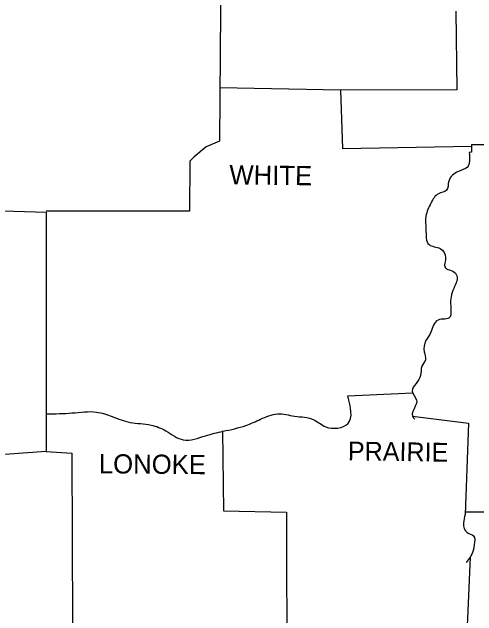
# Model space of a CAD drawing. Extents: x -117616 to 64730, y 54117 to 789866.
# Drawn here: x 64309.8 to 64418.4, y 55726 to 55867.2 of the extents above; entities that cross this region are included whole.
import ezdxf

# ---------------------------------------------------------------- set-up
doc = ezdxf.new("R2010")
doc.units = 0
doc.layers.add('Default', color=7, linetype='Continuous')

msp = doc.modelspace()

# ---------------------------------------------------------------- linework, layer by layer
at = {"layer": 'Default'}
msp.add_line((64417.14, 55836.2), (64429.57, 55836.2), dxfattribs=at)
for points in [[(64310.85, 56002.94), (64311.06, 55978.09), (64309.29, 55977.99), (64309.6, 55951.99), (64302.29, 55950.94), (64302.92, 55943.95), (64305.42, 55940.71), (64305.21, 55932.46), (64291.01, 55931.94), (64290.49, 55919.2), (64277.54, 55918.79), (64276.92, 55903.33), (64277.65, 55902.08), (64277.96, 55877.44), (64300.31, 55875.98), (64299.99, 55820.95), (64317.74, 55820.43), (64317.74, 55764.47), (64303.75, 55763.43), (64302.71, 55751.1), (64279.21, 55751)], [(64300.31, 55875.98), (64353.97, 55875.67), (64358.57, 55877.86), (64358.25, 55837.03), (64355.12, 55835.68), (64352.3, 55833.28), (64351.36, 55832.34), (64351.26, 55820.64), (64317.74, 55820.64)], [(64413.49, 55867.42), (64413.7, 55849.04), (64386.55, 55848.94), (64358.35, 55849.46)], [(64386.55, 55848.94), (64386.97, 55835.26), (64417.14, 55835.8)], [(64417.14, 55836.2), (64417.14, 55834.42), (64416.62, 55834.32)], [(64456.82, 55822.21), (64458.39, 55764.99), (64433.54, 55764.89), (64433.43, 55762.59), (64426.23, 55762.17), (64425.6, 55750.27), (64415.7, 55750.27)], [(64388.22, 55777.42), (64403.46, 55778.15)], [(64403.36, 55772.72), (64416.41, 55771.05), (64415.68, 55749.75)], [(64358.99, 55769.27), (64359.19, 55750.58), (64373.92, 55750.27), (64374.02, 55710.18)], [(64317.74, 55764.47), (64323.8, 55764.05), (64323.9, 55724.17), (64318.47, 55701.51), (64330.06, 55700.99), (64329.96, 55681.03)], [(64416.83, 55739.72), (64415.58, 55711.12), (64407.01, 55710.18), (64407.22, 55701.72), (64410.67, 55701.82), (64410.77, 55698.9), (64415.47, 55698.38), (64415.63, 55693.34)]]:
    msp.add_lwpolyline(points, dxfattribs=at)
for points in [[(64416.62, 55834.32), (64416.1, 55830.87), (64414.12, 55829.93), (64411.82, 55827.64), (64411.3, 55825.55), (64409.42, 55824.71), (64407.64, 55822.52), (64406.49, 55819.49), (64406.49, 55816.36), (64407.22, 55812.81), (64409.83, 55811.87), (64411.09, 55809.78), (64410.88, 55807.59), (64413.38, 55806.13), (64413.8, 55804.88), (64413.38, 55803.52), (64412.24, 55799.66), (64412.34, 55797.05), (64412.13, 55795.9), (64409.31, 55795.17), (64407.64, 55792.35), (64406.49, 55790.36), (64406.08, 55787.75), (64406.39, 55785.87), (64405.55, 55784.41), (64405.24, 55782.22), (64404.2, 55780.34), (64403.26, 55778.56), (64404.3, 55776.48), (64403.99, 55775.01), (64403.36, 55772.72), (64403.88, 55771.99)], [(64317.95, 55773.24), (64323.8, 55773.45), (64329.54, 55773.66), (64333.2, 55772.61), (64337.37, 55771.26), (64342.28, 55770.63), (64345.73, 55769.27), (64349.8, 55767.18), (64355.02, 55768.12), (64359.09, 55769.17), (64364.42, 55770.53), (64367.86, 55771.99), (64371.83, 55773.24), (64375.8, 55772.72), (64380.29, 55771.88), (64383.1, 55770.21), (64388.22, 55770.94), (64388.22, 55777.42)], [(64415.68, 55749.75), (64415.26, 55747.66), (64416.1, 55745.47), (64417.56, 55744.74), (64417.77, 55742.65), (64417.25, 55740.56), (64416.83, 55739.72), (64415.89, 55738.47)]]:
    msp.add_spline(points, degree=3, dxfattribs=at)

# ---------------------------------------------------------------- texts
for s, height, rotation, p in [('WHITE', 4.49, 359.3139, (64360.55, 55826.91)), ('PRAIRIE', 4.386, 359.2116, (64388.22, 55762.38)), ('LONOKE', 4.49, 359.4974, (64330.06, 55759.35))]:
    msp.add_text(s, height=height, rotation=rotation, dxfattribs=at).set_placement(p)

doc.saveas('drawing.dxf')
